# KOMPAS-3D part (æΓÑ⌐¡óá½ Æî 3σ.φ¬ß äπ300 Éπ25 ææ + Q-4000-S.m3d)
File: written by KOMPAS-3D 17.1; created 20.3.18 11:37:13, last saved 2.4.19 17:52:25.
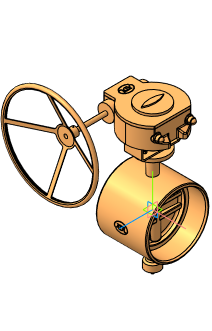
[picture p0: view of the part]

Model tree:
1. Операция без истории:3

Referenced files in C:\Users\kka\KOMPAS_Work\Дисковые повортные затворы ф. Boteli\Стейнвал + редуктор-привода\: Стейнвал ТМ 3х.экс Ду300 Ру25 СС + Q-4000-S.a3d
